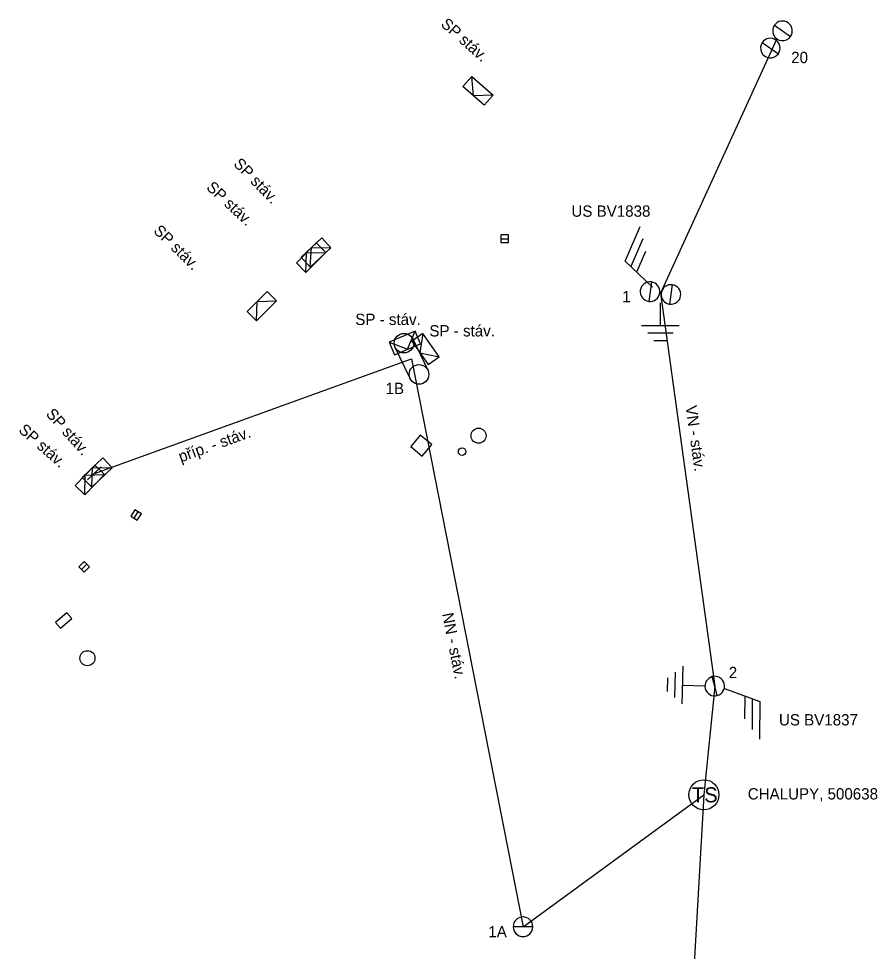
# Model space of a CAD drawing. Extents: x -577028 to -568584, y -1207664 to -1202947.
# Drawn here: x -573494.8 to -573437.8, y -1206292.1 to -1206230.3 of the extents above; entities that cross this region are included whole.
import ezdxf

# ---------------------------------------------------------------- set-up
doc = ezdxf.new("R2010")
doc.units = 0
for name, color, linetype in [('CIZÍ_NADZEM', 7, 'Continuous'), ('ELE_EON', 7, 'Continuous'), ('ELE_EON_POPIS', 7, 'Continuous')]:
    doc.layers.add(name, color=color, linetype=linetype)

msp = doc.modelspace()

# ---------------------------------------------------------------- linework, layer by layer
at = {"layer": 'CIZÍ_NADZEM'}
for p, q in [((-573462.76, -1206244.87), (-573462.26, -1206244.87)), ((-573468.104, -1206257.886), (-573468.744, -1206258.654)), ((-573467.336, -1206258.526), (-573468.104, -1206257.886)), ((-573468.744, -1206258.654), (-573467.976, -1206259.294)), ((-573467.976, -1206259.294), (-573467.336, -1206258.526)), ((-573487.096, -1206263.4), (-573486.824, -1206262.98)), ((-573490.587, -1206266.807), (-573490.233, -1206266.453))]:
    msp.add_line(p, q, dxfattribs=at)
for points in [[(-573462.76, -1206245.121), (-573462.26, -1206245.121), (-573462.26, -1206244.62), (-573462.76, -1206244.62)], [(-573486.885, -1206263.536), (-573486.613, -1206263.116), (-573487.034, -1206262.844), (-573487.306, -1206263.264)], [(-573490.409, -1206266.984), (-573490.055, -1206266.63), (-573490.41, -1206266.276), (-573490.764, -1206266.63)], [(-573491.971, -1206270.708), (-573491.219, -1206270.048), (-573491.549, -1206269.672), (-573492.301, -1206270.332)]]:
    msp.add_lwpolyline(points, close=True, dxfattribs=at)
for centre, radius in [((-573464.24, -1206257.93), 0.5), ((-573465.33, -1206258.99), 0.25), ((-573490.19, -1206272.69), 0.5)]:
    msp.add_circle(centre, radius, dxfattribs=at)
at = {"layer": 'ELE_EON'}
for p, q in [((-573444.609, -1206230.704), (-573443.546, -1206231.451)), ((-573445.414, -1206231.849), (-573444.351, -1206232.596)), ((-573454.517, -1206246.351), (-573453.514, -1206244.061)), ((-573454.119, -1206246.689), (-573453.317, -1206244.857)), ((-573453.741, -1206247.072), (-573453.14, -1206245.698)), ((-573452.708, -1206248.076), (-573454.517, -1206246.351)), ((-573452.776, -1206247.732), (-573452.951, -1206249.02)), ((-573451.389, -1206247.92), (-573451.564, -1206249.208)), ((-573452.17, -1206250.62), (-573452.17, -1206249.12)), ((-573453.42, -1206250.62), (-573450.92, -1206250.62)), ((-573453.02, -1206251.12), (-573451.32, -1206251.12)), ((-573468.602, -1206251.512), (-573467.606, -1206253.585)), ((-573452.62, -1206251.62), (-573451.72, -1206251.62)), ((-573468.778, -1206254.148), (-573469.774, -1206252.075)), ((-573490.176, -1206260.867), (-573489.284, -1206259.993)), ((-573451.192, -1206273.606), (-573451.246, -1206275.305)), ((-573450.679, -1206273.222), (-573450.759, -1206275.721)), ((-573451.704, -1206273.99), (-573451.733, -1206274.89)), ((-573448.4, -1206275.167), (-573448.74, -1206273.913)), ((-573450.719, -1206274.472), (-573449.22, -1206274.519)), ((-573447.921, -1206274.69), (-573445.578, -1206275.563)), ((-573446.575, -1206275.206), (-573446.587, -1206276.706)), ((-573446.077, -1206275.41), (-573446.092, -1206277.41)), ((-573445.578, -1206275.563), (-573445.598, -1206278.063)), ((-573460.64, -1206290.5), (-573461.94, -1206290.5))]:
    msp.add_line(p, q, dxfattribs=at)
for points in [[(-573444.48, -1206231.65), (-573452.17, -1206248.47), (-573448.57, -1206274.54), (-573449.29, -1206281.75)], [(-573463.278, -1206235.341), (-573464.576, -1206235.394), (-573464.682, -1206234.099)], [(-573475.693, -1206247.103), (-573475.666, -1206245.804), (-573474.367, -1206245.777)], [(-573475.406, -1206246.749), (-573475.333, -1206245.451), (-573474.034, -1206245.471)], [(-573478.963, -1206250.323), (-573478.936, -1206249.024), (-573477.637, -1206248.997)], [(-573470.169, -1206251.737), (-573468.955, -1206252.201), (-573468.442, -1206251.007)], [(-573467.929, -1206251.155), (-573468.13, -1206252.439), (-573466.856, -1206252.693)], [(-573489.73, -1206260.43), (-573468.69, -1206252.83)], [(-573468.69, -1206252.83), (-573461.29, -1206290.5), (-573449.29, -1206281.75)], [(-573489.908, -1206261.348), (-573489.852, -1206260.049), (-573488.552, -1206260.052)], [(-573490.352, -1206261.854), (-573490.347, -1206260.554), (-573489.048, -1206260.506)], [(-573449.29, -1206281.75), (-573450.84, -1206308.78)]]:
    msp.add_lwpolyline(points, dxfattribs=at)
for points in [[(-573463.874, -1206236.015), (-573465.279, -1206234.773), (-573464.682, -1206234.099), (-573463.278, -1206235.341)], [(-573476.329, -1206246.467), (-573475.003, -1206245.141), (-573474.367, -1206245.777), (-573475.693, -1206247.103)], [(-573476.019, -1206246.09), (-573474.647, -1206244.812), (-573474.034, -1206245.471), (-573475.406, -1206246.749)], [(-573479.599, -1206249.687), (-573478.273, -1206248.361), (-573477.637, -1206248.997), (-573478.963, -1206250.323)], [(-573469.819, -1206252.566), (-573468.092, -1206251.837), (-573468.442, -1206251.007), (-573470.169, -1206251.737)], [(-573468.667, -1206251.671), (-573467.594, -1206253.208), (-573466.856, -1206252.693), (-573467.929, -1206251.155)], [(-573490.53, -1206260.697), (-573489.174, -1206259.402), (-573488.552, -1206260.052), (-573489.908, -1206261.348)], [(-573490.999, -1206261.228), (-573489.695, -1206259.88), (-573489.048, -1206260.506), (-573490.352, -1206261.854)]]:
    msp.add_lwpolyline(points, close=True, dxfattribs=at)
for centre, radius in [((-573469.188, -1206251.793), 0.65), ((-573468.192, -1206253.867), 0.65), ((-573449.29, -1206281.75), 1)]:
    msp.add_circle(centre, radius, dxfattribs=at)
for centre, start, end in [((-573444.077, -1206231.077), 144.88653, 324.88653), ((-573444.077, -1206231.077), 324.88653, 144.88653), ((-573444.883, -1206232.223), 324.88653, 144.88653), ((-573444.883, -1206232.223), 144.88653, 324.88653), ((-573452.864, -1206248.376), 82.25101, 262.25101), ((-573452.864, -1206248.376), 262.25101, 82.25101), ((-573451.476, -1206248.564), 82.25101, 262.25101), ((-573451.476, -1206248.564), 262.25101, 82.25101), ((-573448.57, -1206274.54), 105.12402, 285.12402), ((-573448.57, -1206274.54), 285.12402, 105.12402), ((-573461.29, -1206290.5), 0, 180), ((-573461.29, -1206290.5), 180, 0)]:
    msp.add_arc(centre, 0.65, start, end, dxfattribs=at)

# ---------------------------------------------------------------- texts
msp.add_text('TS', height=1, dxfattribs=at).set_placement((-573450.083, -1206282.25))
at = {"layer": 'ELE_EON_POPIS'}
for s, rotation, p in [('SP stáv.', 318.35243, (-573466.8, -1206230.71)), ('SP stáv.', 314.27709, (-573480.55, -1206239.95)), ('SP stáv.', 316.99325, (-573482.35, -1206241.53)), ('SP stáv.', 315.59369, (-573485.86, -1206244.4)), ('SP stáv.', 311.6746, (-573492.99, -1206256.52)), ('VN - stáv.', 277.86224, (-573450.51, -1206255.98)), ('SP stáv.', 318.45332, (-573494.81, -1206257.63)), ('příp. - stáv.', 19.86055, (-573483.99, -1206259.71)), ('NN - stáv.', 281.11384, (-573466.66, -1206269.75))]:
    msp.add_text(s, height=0.75, rotation=rotation, dxfattribs=at).set_placement(p)
for s, p in [('20', (-573443.5, -1206233.22)), ('US BV1838', (-573458.08, -1206243.41)), ('1', (-573454.71, -1206249.08)), ('SP - stáv.', (-573472.42, -1206250.59)), ('SP - stáv.', (-573467.5, -1206251.35)), ('1B', (-573470.41, -1206255.17)), ('2', (-573447.64, -1206274.01)), ('US BV1837', (-573444.31, -1206277.15)), ('CHALUPY, 500638', (-573446.38, -1206282.06)), ('1A', (-573463.59, -1206291.2))]:
    msp.add_text(s, height=0.75, dxfattribs=at).set_placement(p)

doc.saveas('drawing.dxf')
